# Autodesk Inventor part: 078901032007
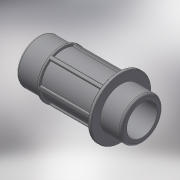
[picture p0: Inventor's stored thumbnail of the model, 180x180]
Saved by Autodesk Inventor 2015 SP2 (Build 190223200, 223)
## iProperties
Created: 2018-02
Part Number: 078901032007
Material: Generic
Description: PLASSON THREADED MALE ADAPTOR 32-3/4"
Document SubType Name: Modeling
Designer: KIM
Density: 1 g/cm^3
Appearance: Default
Author: KIM
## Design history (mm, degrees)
derived "078901.ipt"
feature "Solid1::078901.ipt"
tag "TaggingFeature1"
body "Solid1"
other parameters: "d4" = 1.32205, "d14" = 2.11528, "d15" = 1.05764, "d17" = 0, "d20" = 360 deg, "d40" = 18, "d41" = 26.441, "d45" = 29.0851, "d46" = 18.5087, "d47" = 1.8, "d77" = 86, "d78" = 32, "d85" = 0.26441, "d91" = 17.2, "d103" = 19.78, "d104" = 46, "d105" = 0.26441, "R_" = 26.441, "E_" = 46, "l_2" = 18, "l_" = 86, "d_" = 32
